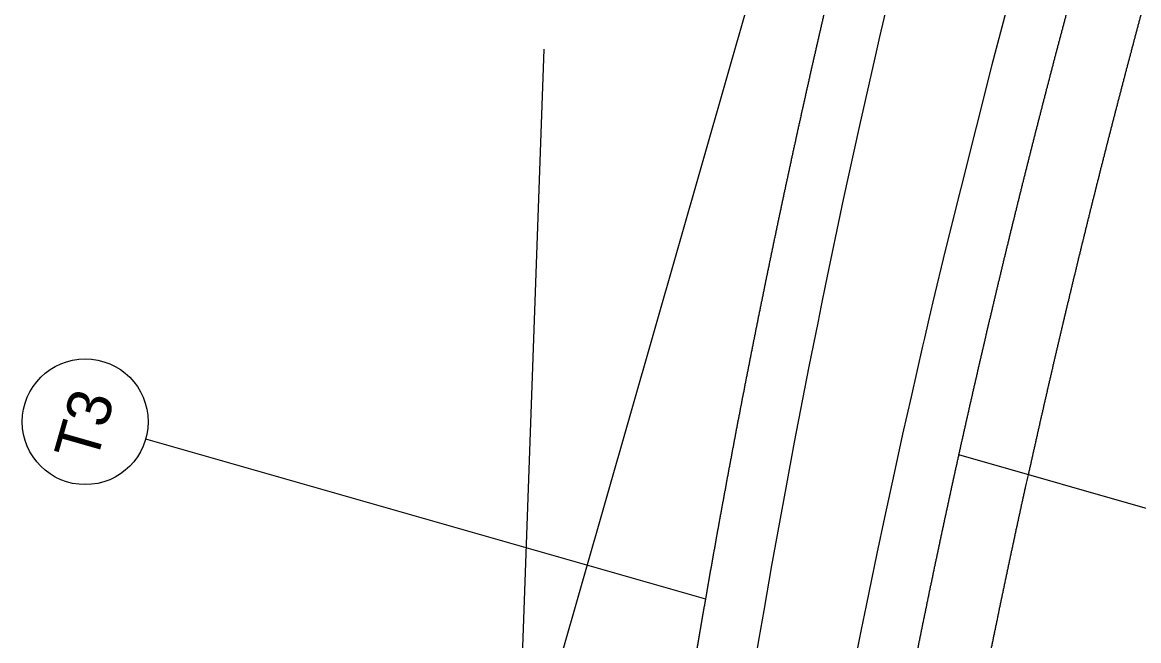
# Model space of a CAD drawing. Extents: x 1657109 to 2100937, y 684916 to 883211.
# Drawn here: x 2097654.9 to 2097894.5, y 688873.2 to 689006 of the extents above; entities that cross this region are included whole.
import ezdxf

# ---------------------------------------------------------------- set-up
doc = ezdxf.new("R2010")
doc.units = 0
for name, color, linetype in [('Prop CMT Pvmt Gravel', 7, 'Continuous'), ('Prop EOT', 7, 'Continuous'), ('Prop Sign E Chevron Right', 7, 'Continuous'), ('Scratch_Level_7', 7, 'Continuous')]:
    doc.layers.add(name, color=color, linetype=linetype)

msp = doc.modelspace()

# ---------------------------------------------------------------- linework, layer by layer
at = {"layer": 'Prop CMT Pvmt Gravel'}
for p, q in [((2097801.56, 688882.06), (2097681.35, 688916.48)), ((2097992.05, 688874.13), (2097855.92, 688913.09))]:
    msp.add_line(p, q, dxfattribs=at)
msp.add_circle((2097668.37, 688920.19), 13.5, dxfattribs=at)
at = {"layer": 'Prop EOT'}
for points in [[(2097826.59, 689005.96), (2097826.78, 689006.79), (2097826.97, 689007.63), (2097827.16, 689008.46), (2097827.36, 689009.29), (2097827.55, 689010.12), (2097827.74, 689010.96), (2097827.94, 689011.79), (2097828.13, 689012.62), (2097828.33, 689013.45), (2097828.52, 689014.28), (2097828.72, 689015.12), (2097828.91, 689015.95), (2097829.11, 689016.78), (2097829.3, 689017.61), (2097829.5, 689018.44), (2097829.7, 689019.28), (2097829.89, 689020.11), (2097830.09, 689020.94), (2097830.29, 689021.77), (2097830.49, 689022.6), (2097830.68, 689023.43), (2097830.88, 689024.27), (2097831.08, 689025.1), (2097831.28, 689025.93), (2097831.48, 689026.76), (2097831.68, 689027.59), (2097831.88, 689028.42), (2097832.08, 689029.25), (2097832.28, 689030.08), (2097832.48, 689030.91), (2097832.68, 689031.74), (2097832.88, 689032.57), (2097833.09, 689033.41), (2097833.29, 689034.24), (2097833.49, 689035.07), (2097833.69, 689035.9), (2097833.9, 689036.73), (2097834.1, 689037.56), (2097834.3, 689038.39), (2097834.51, 689039.22), (2097834.71, 689040.05), (2097834.92, 689040.88), (2097835.12, 689041.71), (2097835.33, 689042.54), (2097835.53, 689043.37), (2097835.74, 689044.2), (2097835.94, 689045.03), (2097836.15, 689045.86), (2097836.36, 689046.69), (2097836.56, 689047.52), (2097836.77, 689048.34), (2097836.98, 689049.17), (2097837.19, 689050), (2097837.4, 689050.83), (2097837.6, 689051.66), (2097837.81, 689052.49), (2097838.02, 689053.32), (2097838.23, 689054.15), (2097838.44, 689054.98), (2097838.65, 689055.81), (2097838.86, 689056.63), (2097839.07, 689057.46), (2097839.28, 689058.29), (2097839.5, 689059.12), (2097839.71, 689059.95), (2097839.92, 689060.78), (2097840.13, 689061.6), (2097840.34, 689062.43), (2097840.56, 689063.26), (2097840.77, 689064.09), (2097840.98, 689064.92), (2097841.2, 689065.74), (2097841.63, 689067.4)], [(2097875.33, 688993.74), (2097875.54, 688994.55), (2097875.75, 688995.36), (2097875.96, 688996.17), (2097876.17, 688996.98), (2097876.38, 688997.79), (2097876.6, 688998.6), (2097876.81, 688999.4), (2097877.02, 689000.21), (2097877.23, 689001.02), (2097877.45, 689001.83), (2097877.66, 689002.64), (2097877.87, 689003.45), (2097878.09, 689004.25), (2097878.3, 689005.06), (2097878.52, 689005.87), (2097878.73, 689006.68), (2097878.95, 689007.49), (2097879.16, 689008.29), (2097879.38, 689009.1), (2097879.59, 689009.91), (2097879.81, 689010.72), (2097880.03, 689011.52), (2097880.24, 689012.33), (2097880.46, 689013.14), (2097880.68, 689013.95), (2097880.9, 689014.75), (2097881.12, 689015.56), (2097881.33, 689016.37), (2097881.55, 689017.17), (2097881.77, 689017.98), (2097881.99, 689018.79), (2097882.21, 689019.59), (2097882.43, 689020.4), (2097882.65, 689021.21), (2097882.87, 689022.01), (2097883.09, 689022.82), (2097883.31, 689023.62), (2097883.54, 689024.43), (2097883.76, 689025.24), (2097883.98, 689026.04), (2097884.2, 689026.85), (2097884.42, 689027.65), (2097884.65, 689028.46), (2097884.87, 689029.27), (2097885.09, 689030.07), (2097885.32, 689030.88), (2097885.54, 689031.68), (2097885.77, 689032.49), (2097885.99, 689033.29), (2097886.22, 689034.1), (2097886.44, 689034.9), (2097886.67, 689035.71), (2097886.89, 689036.51), (2097887.12, 689037.32), (2097887.35, 689038.12), (2097887.57, 689038.92), (2097887.8, 689039.73), (2097888.03, 689040.53), (2097888.25, 689041.34), (2097888.48, 689042.14), (2097888.71, 689042.95), (2097888.94, 689043.75), (2097889.17, 689044.55), (2097889.4, 689045.36), (2097889.63, 689046.16), (2097889.86, 689046.97), (2097890.09, 689047.77), (2097890.32, 689048.57), (2097890.55, 689049.38), (2097890.78, 689050.18), (2097891.01, 689050.98), (2097891.24, 689051.79), (2097891.7, 689053.39)], [(2097813.23, 688944.17), (2097813.4, 688945), (2097813.57, 688945.84), (2097813.74, 688946.68), (2097813.91, 688947.51), (2097814.08, 688948.35), (2097814.25, 688949.19), (2097814.42, 688950.03), (2097814.59, 688950.86), (2097814.76, 688951.7), (2097814.93, 688952.54), (2097815.11, 688953.37), (2097815.28, 688954.21), (2097815.45, 688955.05), (2097815.63, 688955.88), (2097815.8, 688956.72), (2097815.97, 688957.55), (2097816.15, 688958.39), (2097816.32, 688959.23), (2097816.5, 688960.06), (2097816.67, 688960.9), (2097816.85, 688961.74), (2097817.02, 688962.57), (2097817.2, 688963.41), (2097817.38, 688964.24), (2097817.55, 688965.08), (2097817.73, 688965.92), (2097817.91, 688966.75), (2097818.08, 688967.59), (2097818.26, 688968.42), (2097818.44, 688969.26), (2097818.62, 688970.09), (2097818.8, 688970.93), (2097818.98, 688971.76), (2097819.16, 688972.6), (2097819.34, 688973.43), (2097819.52, 688974.27), (2097819.7, 688975.1), (2097819.88, 688975.94), (2097820.06, 688976.77), (2097820.24, 688977.61), (2097820.42, 688978.44), (2097820.6, 688979.28), (2097820.79, 688980.11), (2097820.97, 688980.95), (2097821.15, 688981.78), (2097821.33, 688982.62), (2097821.52, 688983.45), (2097821.7, 688984.29), (2097821.88, 688985.12), (2097822.07, 688985.96), (2097822.25, 688986.79), (2097822.44, 688987.62), (2097822.62, 688988.46), (2097822.81, 688989.29), (2097823, 688990.13), (2097823.18, 688990.96), (2097823.37, 688991.79), (2097823.56, 688992.63), (2097823.74, 688993.46), (2097823.93, 688994.3), (2097824.12, 688995.13), (2097824.31, 688995.96), (2097824.49, 688996.8), (2097824.68, 688997.63), (2097824.87, 688998.46), (2097825.06, 688999.3), (2097825.25, 689000.13), (2097825.44, 689000.96), (2097825.63, 689001.8), (2097825.82, 689002.63), (2097826.01, 689003.46), (2097826.2, 689004.29), (2097826.39, 689005.13), (2097826.59, 689005.96)], [(2097860.58, 688933.66), (2097860.76, 688934.47), (2097860.95, 688935.29), (2097861.14, 688936.1), (2097861.33, 688936.92), (2097861.52, 688937.73), (2097861.71, 688938.54), (2097861.9, 688939.36), (2097862.09, 688940.17), (2097862.28, 688940.99), (2097862.47, 688941.8), (2097862.67, 688942.61), (2097862.86, 688943.43), (2097863.05, 688944.24), (2097863.24, 688945.06), (2097863.43, 688945.87), (2097863.63, 688946.68), (2097863.82, 688947.5), (2097864.01, 688948.31), (2097864.21, 688949.12), (2097864.4, 688949.94), (2097864.6, 688950.75), (2097864.79, 688951.56), (2097864.99, 688952.38), (2097865.18, 688953.19), (2097865.38, 688954), (2097865.57, 688954.82), (2097865.77, 688955.63), (2097865.97, 688956.44), (2097866.16, 688957.25), (2097866.36, 688958.07), (2097866.56, 688958.88), (2097866.76, 688959.69), (2097866.95, 688960.5), (2097867.15, 688961.32), (2097867.35, 688962.13), (2097867.55, 688962.94), (2097867.75, 688963.75), (2097867.95, 688964.56), (2097868.15, 688965.38), (2097868.35, 688966.19), (2097868.55, 688967), (2097868.75, 688967.81), (2097868.95, 688968.62), (2097869.15, 688969.43), (2097869.35, 688970.25), (2097869.55, 688971.06), (2097869.76, 688971.87), (2097869.96, 688972.68), (2097870.16, 688973.49), (2097870.37, 688974.3), (2097870.57, 688975.11), (2097870.77, 688975.92), (2097870.98, 688976.73), (2097871.18, 688977.54), (2097871.39, 688978.36), (2097871.59, 688979.17), (2097871.8, 688979.98), (2097872, 688980.79), (2097872.21, 688981.6), (2097872.41, 688982.41), (2097872.62, 688983.22), (2097872.83, 688984.03), (2097873.03, 688984.84), (2097873.24, 688985.65), (2097873.45, 688986.46), (2097873.66, 688987.27), (2097873.86, 688988.08), (2097874.07, 688988.89), (2097874.28, 688989.7), (2097874.49, 688990.51), (2097874.7, 688991.32), (2097874.91, 688992.12), (2097875.12, 688992.93), (2097875.33, 688993.74)], [(2097801.56, 688882.06), (2097801.71, 688882.91), (2097801.85, 688883.75), (2097802, 688884.59), (2097802.15, 688885.43), (2097802.3, 688886.27), (2097802.44, 688887.11), (2097802.59, 688887.95), (2097802.74, 688888.79), (2097802.89, 688889.63), (2097803.04, 688890.47), (2097803.19, 688891.31), (2097803.34, 688892.15), (2097803.49, 688892.99), (2097803.64, 688893.83), (2097803.79, 688894.68), (2097803.94, 688895.52), (2097804.09, 688896.36), (2097804.24, 688897.2), (2097804.4, 688898.04), (2097804.55, 688898.88), (2097804.7, 688899.72), (2097804.85, 688900.56), (2097805.01, 688901.4), (2097805.16, 688902.24), (2097805.31, 688903.08), (2097805.47, 688903.92), (2097805.62, 688904.76), (2097805.78, 688905.6), (2097805.93, 688906.44), (2097806.09, 688907.27), (2097806.24, 688908.11), (2097806.4, 688908.95), (2097806.55, 688909.79), (2097806.71, 688910.63), (2097806.87, 688911.47), (2097807.03, 688912.31), (2097807.18, 688913.15), (2097807.34, 688913.99), (2097807.5, 688914.83), (2097807.66, 688915.67), (2097807.82, 688916.51), (2097807.98, 688917.35), (2097808.13, 688918.19), (2097808.29, 688919.02), (2097808.45, 688919.86), (2097808.61, 688920.7), (2097808.78, 688921.54), (2097808.94, 688922.38), (2097809.1, 688923.22), (2097809.26, 688924.06), (2097809.42, 688924.9), (2097809.58, 688925.73), (2097809.75, 688926.57), (2097809.91, 688927.41), (2097810.07, 688928.25), (2097810.23, 688929.09), (2097810.4, 688929.93), (2097810.56, 688930.76), (2097810.73, 688931.6), (2097810.89, 688932.44), (2097811.06, 688933.28), (2097811.22, 688934.12), (2097811.39, 688934.95), (2097811.55, 688935.79), (2097811.72, 688936.63), (2097811.89, 688937.47), (2097812.05, 688938.3), (2097812.22, 688939.14), (2097812.39, 688939.98), (2097812.55, 688940.82), (2097812.72, 688941.65), (2097812.89, 688942.49), (2097813.06, 688943.33), (2097813.23, 688944.17)], [(2097847.46, 688873.18), (2097847.63, 688874), (2097847.79, 688874.82), (2097847.96, 688875.64), (2097848.13, 688876.46), (2097848.29, 688877.28), (2097848.46, 688878.1), (2097848.63, 688878.91), (2097848.8, 688879.73), (2097848.97, 688880.55), (2097849.14, 688881.37), (2097849.3, 688882.19), (2097849.47, 688883.01), (2097849.64, 688883.83), (2097849.81, 688884.65), (2097849.99, 688885.47), (2097850.16, 688886.29), (2097850.33, 688887.1), (2097850.5, 688887.92), (2097850.67, 688888.74), (2097850.84, 688889.56), (2097851.01, 688890.38), (2097851.19, 688891.2), (2097851.36, 688892.01), (2097851.53, 688892.83), (2097851.71, 688893.65), (2097851.88, 688894.47), (2097852.05, 688895.29), (2097852.23, 688896.11), (2097852.4, 688896.92), (2097852.58, 688897.74), (2097852.75, 688898.56), (2097852.93, 688899.38), (2097853.11, 688900.19), (2097853.28, 688901.01), (2097853.46, 688901.83), (2097853.64, 688902.65), (2097853.81, 688903.46), (2097853.99, 688904.28), (2097854.17, 688905.1), (2097854.35, 688905.92), (2097854.52, 688906.73), (2097854.7, 688907.55), (2097854.88, 688908.37), (2097855.06, 688909.18), (2097855.24, 688910), (2097855.42, 688910.82), (2097855.6, 688911.63), (2097855.78, 688912.45), (2097855.96, 688913.27), (2097856.14, 688914.08), (2097856.32, 688914.9), (2097856.51, 688915.72), (2097856.69, 688916.53), (2097856.87, 688917.35), (2097857.05, 688918.16), (2097857.23, 688918.98), (2097857.42, 688919.8), (2097857.6, 688920.61), (2097857.78, 688921.43), (2097857.97, 688922.24), (2097858.15, 688923.06), (2097858.34, 688923.88), (2097858.52, 688924.69), (2097858.71, 688925.51), (2097858.89, 688926.32), (2097859.08, 688927.14), (2097859.27, 688927.95), (2097859.45, 688928.77), (2097859.64, 688929.58), (2097859.83, 688930.4), (2097860.01, 688931.21), (2097860.2, 688932.03), (2097860.39, 688932.84), (2097860.58, 688933.66)], [(2097791.59, 688819.7), (2097791.71, 688820.54), (2097791.84, 688821.39), (2097791.96, 688822.23), (2097792.09, 688823.08), (2097792.21, 688823.92), (2097792.34, 688824.77), (2097792.46, 688825.61), (2097792.59, 688826.45), (2097792.71, 688827.3), (2097792.84, 688828.14), (2097792.97, 688828.99), (2097793.09, 688829.83), (2097793.22, 688830.67), (2097793.35, 688831.52), (2097793.47, 688832.36), (2097793.6, 688833.2), (2097793.73, 688834.05), (2097793.86, 688834.89), (2097793.99, 688835.74), (2097794.12, 688836.58), (2097794.25, 688837.42), (2097794.38, 688838.27), (2097794.51, 688839.11), (2097794.64, 688839.95), (2097794.77, 688840.8), (2097794.9, 688841.64), (2097795.03, 688842.48), (2097795.16, 688843.33), (2097795.3, 688844.17), (2097795.43, 688845.01), (2097795.56, 688845.85), (2097795.69, 688846.7), (2097795.83, 688847.54), (2097795.96, 688848.38), (2097796.09, 688849.23), (2097796.23, 688850.07), (2097796.36, 688850.91), (2097796.5, 688851.76), (2097796.63, 688852.6), (2097796.77, 688853.44), (2097796.9, 688854.28), (2097797.04, 688855.13), (2097797.18, 688855.97), (2097797.31, 688856.81), (2097797.45, 688857.65), (2097797.59, 688858.5), (2097797.73, 688859.34), (2097797.86, 688860.18), (2097798, 688861.02), (2097798.14, 688861.86), (2097798.28, 688862.71), (2097798.42, 688863.55), (2097798.56, 688864.39), (2097798.7, 688865.23), (2097798.84, 688866.08), (2097798.98, 688866.92), (2097799.12, 688867.76), (2097799.26, 688868.6), (2097799.4, 688869.44), (2097799.54, 688870.28), (2097799.69, 688871.13), (2097799.83, 688871.97), (2097799.97, 688872.81), (2097800.11, 688873.65), (2097800.26, 688874.49), (2097800.4, 688875.33), (2097800.55, 688876.18), (2097800.69, 688877.02), (2097800.83, 688877.86), (2097800.98, 688878.7), (2097801.12, 688879.54), (2097801.27, 688880.38), (2097801.42, 688881.22), (2097801.56, 688882.06)], [(2097835.99, 688812.35), (2097836.13, 688813.17), (2097836.28, 688814), (2097836.42, 688814.82), (2097836.56, 688815.65), (2097836.71, 688816.47), (2097836.86, 688817.29), (2097837, 688818.12), (2097837.15, 688818.94), (2097837.29, 688819.77), (2097837.44, 688820.59), (2097837.59, 688821.41), (2097837.73, 688822.24), (2097837.88, 688823.06), (2097838.03, 688823.88), (2097838.18, 688824.71), (2097838.33, 688825.53), (2097838.48, 688826.35), (2097838.63, 688827.18), (2097838.77, 688828), (2097838.92, 688828.82), (2097839.07, 688829.65), (2097839.22, 688830.47), (2097839.38, 688831.29), (2097839.53, 688832.11), (2097839.68, 688832.94), (2097839.83, 688833.76), (2097839.98, 688834.58), (2097840.13, 688835.4), (2097840.29, 688836.23), (2097840.44, 688837.05), (2097840.59, 688837.87), (2097840.75, 688838.69), (2097840.9, 688839.52), (2097841.05, 688840.34), (2097841.21, 688841.16), (2097841.36, 688841.98), (2097841.52, 688842.81), (2097841.67, 688843.63), (2097841.83, 688844.45), (2097841.98, 688845.27), (2097842.14, 688846.09), (2097842.3, 688846.91), (2097842.45, 688847.74), (2097842.61, 688848.56), (2097842.77, 688849.38), (2097842.92, 688850.2), (2097843.08, 688851.02), (2097843.24, 688851.84), (2097843.4, 688852.66), (2097843.56, 688853.49), (2097843.72, 688854.31), (2097843.88, 688855.13), (2097844.04, 688855.95), (2097844.2, 688856.77), (2097844.36, 688857.59), (2097844.52, 688858.41), (2097844.68, 688859.23), (2097844.84, 688860.05), (2097845, 688860.87), (2097845.16, 688861.7), (2097845.32, 688862.52), (2097845.49, 688863.34), (2097845.65, 688864.16), (2097845.81, 688864.98), (2097845.98, 688865.8), (2097846.14, 688866.62), (2097846.3, 688867.44), (2097846.47, 688868.26), (2097846.63, 688869.08), (2097846.8, 688869.9), (2097846.96, 688870.72), (2097847.13, 688871.54), (2097847.29, 688872.36), (2097847.46, 688873.18)]]:
    msp.add_spline(points, degree=3, dxfattribs=at)
at = {"layer": 'Prop Sign E Chevron Right'}
for p, q in [((2097739.07, 688759.59), (2097851.61, 689153.37)), ((2097746.67, 688429.22), (2097766.87, 689000.21))]:
    msp.add_line(p, q, dxfattribs=at)
for points in [[(2097890.35, 688989.86), (2097890.56, 688990.66), (2097890.77, 688991.47), (2097890.98, 688992.27), (2097891.19, 688993.08), (2097891.4, 688993.88), (2097891.61, 688994.69), (2097891.82, 688995.49), (2097892.03, 688996.29), (2097892.24, 688997.1), (2097892.46, 688997.9), (2097892.67, 688998.71), (2097892.88, 688999.51), (2097893.09, 689000.31), (2097893.31, 689001.12), (2097893.52, 689001.92), (2097893.73, 689002.72), (2097893.95, 689003.53), (2097894.16, 689004.33), (2097894.38, 689005.14), (2097894.59, 689005.94), (2097894.81, 689006.74), (2097895.02, 689007.54), (2097895.24, 689008.35), (2097895.46, 689009.15), (2097895.67, 689009.95), (2097895.89, 689010.76), (2097896.11, 689011.56), (2097896.32, 689012.36), (2097896.54, 689013.16), (2097896.76, 689013.97), (2097896.98, 689014.77), (2097897.2, 689015.57), (2097897.41, 689016.37), (2097897.63, 689017.18), (2097897.85, 689017.98), (2097898.07, 689018.78), (2097898.29, 689019.58), (2097898.51, 689020.38), (2097898.73, 689021.19), (2097898.95, 689021.99), (2097899.18, 689022.79), (2097899.4, 689023.59), (2097899.62, 689024.39), (2097899.84, 689025.19), (2097900.06, 689025.99), (2097900.29, 689026.79), (2097900.51, 689027.6), (2097900.73, 689028.4), (2097900.96, 689029.2), (2097901.18, 689030), (2097901.4, 689030.8), (2097901.63, 689031.6), (2097901.85, 689032.4), (2097902.08, 689033.2), (2097902.3, 689034), (2097902.53, 689034.8), (2097902.76, 689035.6), (2097902.98, 689036.4), (2097903.21, 689037.2), (2097903.43, 689038), (2097903.66, 689038.8), (2097903.89, 689039.6), (2097904.12, 689040.4), (2097904.13, 689040.46)], [(2097875.67, 688930.09), (2097875.86, 688930.9), (2097876.05, 688931.71), (2097876.23, 688932.52), (2097876.42, 688933.33), (2097876.61, 688934.14), (2097876.8, 688934.95), (2097876.99, 688935.76), (2097877.18, 688936.57), (2097877.37, 688937.38), (2097877.56, 688938.19), (2097877.75, 688939), (2097877.94, 688939.81), (2097878.13, 688940.62), (2097878.32, 688941.43), (2097878.51, 688942.24), (2097878.71, 688943.05), (2097878.9, 688943.86), (2097879.09, 688944.67), (2097879.28, 688945.47), (2097879.48, 688946.28), (2097879.67, 688947.09), (2097879.86, 688947.9), (2097880.06, 688948.71), (2097880.25, 688949.52), (2097880.45, 688950.33), (2097880.64, 688951.14), (2097880.84, 688951.94), (2097881.03, 688952.75), (2097881.23, 688953.56), (2097881.43, 688954.37), (2097881.62, 688955.18), (2097881.82, 688955.99), (2097882.02, 688956.79), (2097882.21, 688957.6), (2097882.41, 688958.41), (2097882.61, 688959.22), (2097882.81, 688960.03), (2097883.01, 688960.83), (2097883.2, 688961.64), (2097883.4, 688962.45), (2097883.6, 688963.26), (2097883.8, 688964.06), (2097884, 688964.87), (2097884.2, 688965.68), (2097884.4, 688966.48), (2097884.6, 688967.29), (2097884.8, 688968.1), (2097885.01, 688968.91), (2097885.21, 688969.71), (2097885.41, 688970.52), (2097885.61, 688971.33), (2097885.82, 688972.13), (2097886.02, 688972.94), (2097886.22, 688973.75), (2097886.42, 688974.55), (2097886.63, 688975.36), (2097886.83, 688976.16), (2097887.04, 688976.97), (2097887.24, 688977.78), (2097887.45, 688978.58), (2097887.65, 688979.39), (2097887.86, 688980.19), (2097888.06, 688981), (2097888.27, 688981.81), (2097888.48, 688982.61), (2097888.68, 688983.42), (2097888.89, 688984.22), (2097889.1, 688985.03), (2097889.31, 688985.83), (2097889.51, 688986.64), (2097889.72, 688987.44), (2097889.93, 688988.25), (2097890.14, 688989.05), (2097890.35, 688989.86)], [(2097870.86, 688908.82), (2097870.9, 688908.99), (2097871.08, 688909.81), (2097871.26, 688910.62), (2097871.44, 688911.43), (2097871.62, 688912.24), (2097871.8, 688913.05), (2097871.98, 688913.87), (2097872.16, 688914.68), (2097872.35, 688915.49), (2097872.53, 688916.3), (2097872.71, 688917.11), (2097872.89, 688917.92), (2097873.08, 688918.74), (2097873.26, 688919.55), (2097873.44, 688920.36), (2097873.63, 688921.17), (2097873.81, 688921.98), (2097874, 688922.79), (2097874.18, 688923.6), (2097874.37, 688924.41), (2097874.55, 688925.23), (2097874.74, 688926.04), (2097874.92, 688926.85), (2097875.11, 688927.66), (2097875.3, 688928.47), (2097875.48, 688929.28), (2097875.67, 688930.09)], [(2097862.54, 688869.76), (2097862.7, 688870.58), (2097862.87, 688871.39), (2097863.03, 688872.21), (2097863.2, 688873.02), (2097863.37, 688873.84), (2097863.53, 688874.65), (2097863.7, 688875.47), (2097863.87, 688876.28), (2097864.04, 688877.1), (2097864.21, 688877.91), (2097864.37, 688878.73), (2097864.54, 688879.54), (2097864.71, 688880.36), (2097864.88, 688881.17), (2097865.05, 688881.99), (2097865.22, 688882.8), (2097865.39, 688883.61), (2097865.56, 688884.43), (2097865.73, 688885.24), (2097865.9, 688886.06), (2097866.08, 688886.87), (2097866.25, 688887.69), (2097866.42, 688888.5), (2097866.59, 688889.31), (2097866.76, 688890.13), (2097866.94, 688890.94), (2097867.11, 688891.75), (2097867.28, 688892.57), (2097867.46, 688893.38), (2097867.63, 688894.2), (2097867.81, 688895.01), (2097867.98, 688895.82), (2097868.16, 688896.64), (2097868.33, 688897.45), (2097868.51, 688898.26), (2097868.68, 688899.07), (2097868.86, 688899.89), (2097869.04, 688900.7), (2097869.21, 688901.51), (2097869.39, 688902.33), (2097869.57, 688903.14), (2097869.74, 688903.95), (2097869.92, 688904.76), (2097870.1, 688905.58), (2097870.28, 688906.39), (2097870.86, 688908.82)]]:
    msp.add_spline(points, degree=3, dxfattribs=at)
at = {"layer": 'Scratch_Level_7'}
for points in [[(2097810.7, 688859.69), (2097813.05, 688873.67), (2097814.08, 688879.64), (2097815.78, 688889.33), (2097818.82, 688906), (2097820.66, 688915.79), (2097823.81, 688932.08), (2097825.68, 688941.4), (2097826.43, 688945.12), (2097827.37, 688949.72), (2097831.18, 688967.89), (2097834.65, 688983.81), (2097837.92, 688998.34), (2097838.95, 689002.86), (2097844.9, 689028.02)], [(2097868.18, 689016.57), (2097862.96, 688996.84), (2097852.97, 688956.94), (2097850.35, 688945.94), (2097849.34, 688941.62), (2097848.53, 688938.17), (2097848.13, 688936.42), (2097845.64, 688925.53), (2097843.84, 688917.49), (2097842, 688909.12), (2097839.95, 688899.65), (2097838.31, 688891.9), (2097835.98, 688880.71), (2097834.94, 688875.6), (2097833.22, 688867.04)]]:
    msp.add_lwpolyline(points, dxfattribs=at)

# ---------------------------------------------------------------- texts
at = {"layer": 'Prop CMT Pvmt Gravel'}
msp.add_text('T3', height=9.45, rotation=74.0259, dxfattribs=at).set_placement((2097670.68, 688911.09))

doc.saveas('drawing.dxf')
